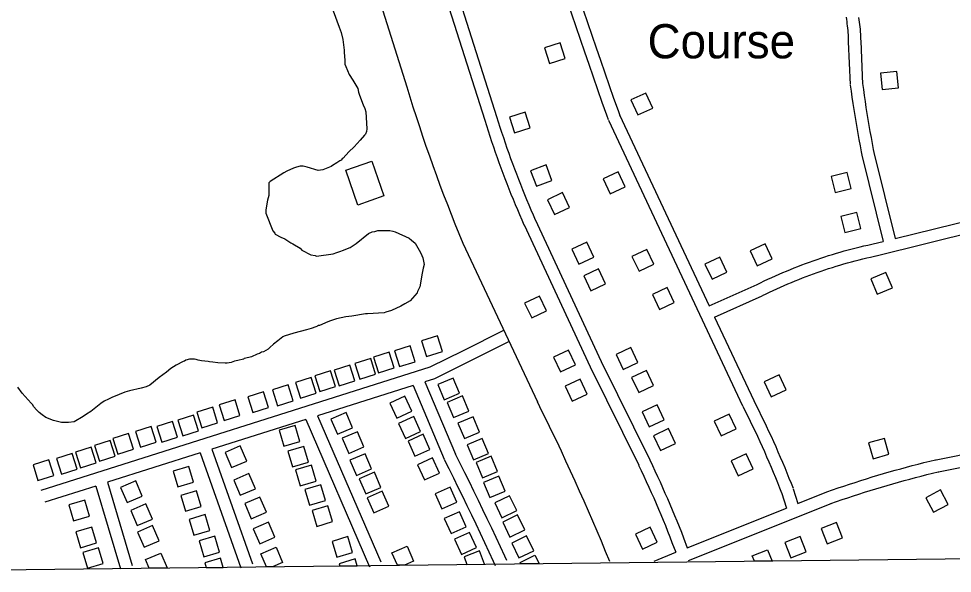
# Model space of a CAD drawing. Extents: x 3683402 to 3721514, y 487807 to 513565.
# Drawn here: x 3688390 to 3690655, y 493222 to 494568 of the extents above; entities that cross this region are included whole.
import ezdxf

# ---------------------------------------------------------------- set-up
doc = ezdxf.new("R2010")
doc.units = 0
for name, color, linetype in [('V-BLDG-IDEN', 7, 'Continuous'), ('V-BLDG-OTLN', 7, 'Continuous'), ('V-GRID-FRAM', 7, 'Continuous'), ('V-ROAD-CNTR', 7, 'Continuous'), ('V-SITE-VEGE', 7, 'Continuous')]:
    doc.layers.add(name, color=color, linetype=linetype)

msp = doc.modelspace()

# ---------------------------------------------------------------- linework, layer by layer
at = {"layer": 'V-BLDG-OTLN'}
for p, q in [((3688977.9, 493269.2), (3689014.6, 493285)), ((3689014.6, 493285), (3689030.5, 493248.3)), ((3689295.7, 493272), (3689332.5, 493287.8)), ((3689332.5, 493287.8), (3689348.3, 493251.1)), ((3689507.8, 493276.1), (3689470.5, 493261.6)), ((3689520.3, 493243.8), (3689507.8, 493276.1)), ((3688697.9, 493255.2), (3688734.7, 493271)), ((3688707, 493234.2), (3688697.9, 493255.2)), ((3688734.7, 493271), (3688750.3, 493234.8)), ((3688879.8, 493259), (3688841.4, 493247.6)), ((3688886.5, 493236.4), (3688879.8, 493259)), ((3688991.5, 493237.6), (3688977.9, 493269.2)), ((3689206, 493256.7), (3689167.6, 493245.3)), ((3689210.9, 493240.2), (3689206, 493256.7)), ((3689309, 493241.3), (3689295.7, 493272)), ((3689470.5, 493261.6), (3689477.6, 493243.3)), ((3689606.6, 493248.1), (3689642.6, 493265.7)), ((3689642.6, 493265.7), (3689652.5, 493245.4)), ((3688750.3, 493234.8), (3688707, 493234.2)), ((3688841.4, 493247.6), (3688844.9, 493235.9)), ((3688844.9, 493235.9), (3688886.5, 493236.4)), ((3689006, 493237.8), (3688991.5, 493237.6)), ((3689030.5, 493248.3), (3689006, 493237.8)), ((3689167.6, 493245.3), (3689169.3, 493239.7)), ((3689169.3, 493239.7), (3689210.9, 493240.2)), ((3689326.1, 493241.5), (3689309, 493241.3)), ((3689348.3, 493251.1), (3689326.1, 493241.5)), ((3689477.6, 493243.3), (3689520.3, 493243.8)), ((3689608.2, 493244.8), (3689606.6, 493248.1)), ((3689652.5, 493245.4), (3689608.2, 493244.8)), ((3690217.9, 493251.7), (3690175.1, 493251.2))]:
    msp.add_line(p, q, dxfattribs=at)
for points in [[(3689715.7, 494471.5), (3689703.7, 494509.7), (3689665.6, 494497.7), (3689677.6, 494459.5)], [(3690480.5, 494435.9), (3690484.6, 494396.1), (3690524.4, 494400.2), (3690520.3, 494440)], [(3689875.5, 494371.1), (3689892.1, 494334.7), (3689928.5, 494351.2), (3689911.9, 494387.7)], [(3689580.8, 494328.9), (3689593, 494290.8), (3689631.1, 494303), (3689618.9, 494341.1)], [(3689276.1, 494137.8), (3689213, 494115.9), (3689183.6, 494200.6), (3689246.7, 494222.5)], [(3689632.1, 494199.1), (3689646, 494161.6), (3689683.5, 494175.5), (3689669.6, 494213)], [(3689861.4, 494160), (3689844.4, 494196.2), (3689808.2, 494179.2), (3689825.2, 494143)], [(3690409.8, 494155.6), (3690400.2, 494194.4), (3690361.4, 494184.8), (3690371, 494146)], [(3689673, 494128.8), (3689690.1, 494092.6), (3689726.3, 494109.7), (3689709.2, 494145.9)], [(3690432.9, 494058.9), (3690423.3, 494097.7), (3690384.4, 494088.2), (3690394, 494049.3)], [(3689732.3, 494008.5), (3689749.4, 493972.3), (3689785.6, 493989.3), (3689768.5, 494025.5)], [(3689931.2, 493971.9), (3689914.2, 494008.1), (3689878, 493991.1), (3689895, 493954.9)], [(3690181.7, 493968.2), (3690218, 493985), (3690201.2, 494021.3), (3690164.9, 494004.6)], [(3690055.1, 493971.9), (3690072.1, 493935.6), (3690108.3, 493952.6), (3690091.3, 493988.9)], [(3689760.8, 493944.1), (3689777.9, 493907.9), (3689814.1, 493924.9), (3689797, 493961.1)], [(3690494.1, 493951.9), (3690457.3, 493936.3), (3690472.9, 493899.5), (3690509.8, 493915.1)], [(3689980.6, 493879.3), (3689963.6, 493915.6), (3689927.4, 493898.6), (3689944.4, 493862.4)], [(3689670.9, 493858.8), (3689653.8, 493895), (3689617.6, 493877.9), (3689634.7, 493841.8)], [(3689379.8, 493748), (3689417.9, 493760), (3689405.8, 493798.2), (3689367.7, 493786.1)], [(3689313.9, 493723.6), (3689352.1, 493735.6), (3689340, 493773.8), (3689301.9, 493761.7)], [(3689263.2, 493708.8), (3689301.3, 493720.9), (3689289.2, 493759), (3689251.1, 493746.9)], [(3689741, 493727.7), (3689724, 493763.9), (3689687.8, 493746.8), (3689704.8, 493710.6)], [(3689839.3, 493752.9), (3689856.3, 493716.7), (3689892.5, 493733.8), (3689875.5, 493770)], [(3689218, 493692.8), (3689256.1, 493704.9), (3689244, 493743), (3689205.9, 493730.9)], [(3689120.7, 493663), (3689158.9, 493675.1), (3689146.8, 493713.3), (3689108.7, 493701.2)], [(3689167.2, 493677), (3689205.3, 493689), (3689193.2, 493727.2), (3689155.1, 493715.1)], [(3689877.2, 493697), (3689894.3, 493660.9), (3689930.5, 493677.9), (3689913.4, 493714.1)], [(3689073.8, 493647.3), (3689112, 493659.4), (3689099.9, 493697.5), (3689061.8, 493685.4)], [(3689407, 493680.2), (3689422.5, 493643.3), (3689459.4, 493658.8), (3689443.9, 493695.7)], [(3689769.4, 493656.6), (3689752.4, 493692.8), (3689716.2, 493675.8), (3689733.2, 493639.6)], [(3690198.5, 493686.6), (3690215.5, 493650.4), (3690251.7, 493667.4), (3690234.7, 493703.6)], [(3688958, 493612.3), (3688996.1, 493624.4), (3688984, 493662.5), (3688945.9, 493650.4)], [(3689017.7, 493628.8), (3689055.9, 493640.9), (3689043.8, 493679), (3689005.6, 493667)], [(3688888.8, 493592.9), (3688926.9, 493604.9), (3688914.9, 493643.1), (3688876.7, 493631)], [(3689343.6, 493615.1), (3689327.2, 493651.6), (3689290.7, 493635.2), (3689307.1, 493598.7)], [(3689429.7, 493636.7), (3689445.2, 493599.9), (3689482.1, 493615.4), (3689466.5, 493652.3)], [(3688834.7, 493574.8), (3688872.8, 493586.8), (3688860.7, 493625), (3688822.6, 493612.9)], [(3689902.6, 493613.6), (3689919.7, 493577.4), (3689955.8, 493594.5), (3689938.8, 493630.6)], [(3688788.4, 493555.8), (3688826.5, 493567.9), (3688814.4, 493606), (3688776.3, 493593.9)], [(3689147.7, 493596.1), (3689163.6, 493559.4), (3689200.3, 493575.3), (3689184.4, 493612)], [(3689364.8, 493565.8), (3689348.4, 493602.3), (3689311.9, 493585.9), (3689328.3, 493549.4)], [(3689455.8, 493586), (3689471.3, 493549.1), (3689508.2, 493564.7), (3689492.6, 493601.5)], [(3690130.9, 493572.2), (3690113.9, 493608.4), (3690077.7, 493591.4), (3690094.7, 493555.2)], [(3688685.8, 493528.1), (3688723.9, 493540.2), (3688711.8, 493578.3), (3688673.7, 493566.2)], [(3688737.2, 493539.9), (3688775.3, 493552), (3688763.2, 493590.1), (3688725.1, 493578)], [(3689071.9, 493542.1), (3689060.5, 493580.4), (3689022.2, 493569.1), (3689033.6, 493530.7)], [(3689930, 493555.9), (3689947.1, 493519.7), (3689983.3, 493536.8), (3689966.2, 493573)], [(3688630.8, 493511), (3688668.9, 493523.1), (3688656.8, 493561.2), (3688618.7, 493549.1)], [(3689175, 493549.9), (3689190.8, 493513.1), (3689227.6, 493529), (3689211.7, 493565.7)], [(3689387.5, 493522.8), (3689371.1, 493559.3), (3689334.6, 493542.9), (3689351, 493506.4)], [(3689477.8, 493533.8), (3689493.3, 493497), (3689530.2, 493512.5), (3689514.6, 493549.3)], [(3690462.8, 493500.1), (3690501.3, 493510.8), (3690490.5, 493549.4), (3690452, 493538.6)], [(3688540.1, 493477.7), (3688578.3, 493489.8), (3688566.2, 493528), (3688528, 493515.9)], [(3688585.8, 493494.1), (3688624, 493506.2), (3688611.9, 493544.3), (3688573.7, 493532.3)], [(3688890.9, 493515.2), (3688906.7, 493478.4), (3688943.5, 493494.3), (3688927.6, 493531)], [(3689093, 493491.4), (3689081.6, 493529.7), (3689043.3, 493518.4), (3689054.7, 493480)], [(3688493.9, 493462.5), (3688532, 493474.6), (3688519.9, 493512.7), (3688481.8, 493500.6)], [(3689193.8, 493496.2), (3689209.7, 493459.4), (3689246.4, 493475.3), (3689230.6, 493512)], [(3689410.6, 493465.3), (3689394.2, 493501.8), (3689357.8, 493485.4), (3689374.2, 493448.9)], [(3689499.8, 493490.7), (3689515.3, 493453.8), (3689552.1, 493469.3), (3689536.6, 493506.2)], [(3690172, 493475.8), (3690155, 493512), (3690118.8, 493495), (3690135.8, 493458.8)], [(3688436.9, 493447), (3688475, 493459.1), (3688462.9, 493497.2), (3688424.8, 493485.1)], [(3688814.4, 493443.1), (3688803, 493481.4), (3688764.7, 493470.1), (3688776, 493431.7)], [(3689111.5, 493445.8), (3689100.1, 493484.2), (3689061.7, 493472.8), (3689073.1, 493434.5)], [(3688911.9, 493448.1), (3688927.7, 493411.3), (3688964.4, 493427.2), (3688948.6, 493463.9)], [(3689216.1, 493451.4), (3689232, 493414.7), (3689268.7, 493430.5), (3689252.9, 493467.3)], [(3689517.9, 493442.5), (3689533.4, 493405.6), (3689570.3, 493421.1), (3689554.8, 493458)], [(3688637.4, 493430.4), (3688653.3, 493393.7), (3688690, 493409.5), (3688674.2, 493446.3)], [(3689134.1, 493398.5), (3689122.7, 493436.8), (3689084.3, 493425.4), (3689095.7, 493387.1)], [(3688832.9, 493384), (3688821.6, 493422.3), (3688783.2, 493410.9), (3688794.6, 493372.6)], [(3689235.5, 493405.4), (3689251.3, 493368.7), (3689288.1, 493384.5), (3689272.2, 493421.2)], [(3689453.1, 493394.5), (3689436.7, 493431), (3689400.2, 493414.6), (3689416.6, 493378.1)], [(3690626.1, 493424.2), (3690590.8, 493405.5), (3690609.5, 493370.2), (3690644.8, 493388.9)], [(3688561.5, 493360.9), (3688550.2, 493399.3), (3688511.8, 493387.9), (3688523.2, 493349.6)], [(3688661.8, 493374.6), (3688677.7, 493337.8), (3688714.4, 493353.7), (3688698.6, 493390.4)], [(3688938.4, 493391.1), (3688954.2, 493354.4), (3688990.9, 493370.2), (3688975.1, 493407)], [(3689545, 493392.6), (3689562.5, 493356.6), (3689598.5, 493374.2), (3689581, 493410.1)], [(3689151.6, 493347.3), (3689140.2, 493385.7), (3689101.9, 493374.3), (3689113.2, 493335.9)], [(3689475.6, 493334.7), (3689459.2, 493371.2), (3689422.7, 493354.8), (3689439.1, 493318.3)], [(3688853.4, 493325.9), (3688842.1, 493364.3), (3688803.7, 493352.9), (3688815.1, 493314.5)], [(3688959.2, 493330.2), (3688975.1, 493293.5), (3689011.8, 493309.3), (3688995.9, 493346.1)], [(3689564.4, 493346), (3689582, 493310), (3689617.9, 493327.6), (3689600.4, 493363.5)], [(3690373.9, 493345.4), (3690336.8, 493330.5), (3690351.7, 493293.4), (3690388.8, 493308.2)], [(3688578.6, 493295.5), (3688567.2, 493333.8), (3688528.9, 493322.5), (3688540.2, 493284.1)], [(3688678.2, 493322), (3688694.1, 493285.3), (3688730.8, 493301.1), (3688715, 493337.8)], [(3689500.5, 493284.3), (3689484.1, 493320.8), (3689447.7, 493304.4), (3689464.1, 493267.9)], [(3689939.4, 493297.6), (3689922.3, 493333.8), (3689886.2, 493316.8), (3689903.2, 493280.6)], [(3688877.3, 493273.4), (3688865.9, 493311.7), (3688827.6, 493300.4), (3688839, 493262)], [(3689200, 493272.6), (3689188.6, 493310.9), (3689150.2, 493299.5), (3689161.6, 493261.2)], [(3689586.3, 493295), (3689603.8, 493259.1), (3689639.7, 493276.6), (3689622.2, 493312.5)], [(3690285.7, 493311.2), (3690248.6, 493296.4), (3690263.5, 493259.2), (3690300.6, 493274.1)], [(3688595.2, 493245.7), (3688583.9, 493284.1), (3688545.5, 493272.7), (3688556.9, 493234.3)]]:
    msp.add_lwpolyline(points, close=True, dxfattribs=at)
for points in [[(3690175.1, 493251.2), (3690169.8, 493264.3), (3690206.9, 493279.2)], [(3690206.9, 493279.2), (3690217.9, 493251.7)]]:
    msp.add_lwpolyline(points, dxfattribs=at)
at = {"layer": 'V-GRID-FRAM'}
msp.add_lwpolyline([(3687448, 511403.5), (3719130.8, 511772.1), (3719350.3, 493590.7), (3687651.7, 493221.8), (3687448, 511403.5)], dxfattribs=at)
at = {"layer": 'V-ROAD-CNTR'}
for points in [[(3689156.9, 494957.3), (3689331.5, 494402.6)], [(3689388.1, 494838.2), (3689549.4, 494330.7)], [(3689359.5, 494829.4), (3689520.8, 494321.6)], [(3689690.6, 494703.3), (3689700.7, 494672.5), (3689710.8, 494641.7), (3689720.9, 494610.9), (3689731.2, 494580.2), (3689741.5, 494549.4), (3689751.9, 494518.7), (3689762.4, 494488), (3689773, 494457.4), (3689783.6, 494426.8), (3689794.4, 494396.2), (3689805.1, 494365.6), (3689816, 494335.1), (3689820.3, 494323.2)], [(3689719.2, 494712.6), (3689729.2, 494681.8), (3689739.3, 494651.1), (3689749.4, 494620.4), (3689759.6, 494589.7), (3689770, 494559), (3689780.3, 494528.4), (3689790.8, 494497.8), (3689801.3, 494467.2), (3689812, 494436.7), (3689822.7, 494406.1), (3689833.4, 494375.6), (3689844.3, 494345.1), (3689848.5, 494333.3)], [(3690397.2, 494571.8), (3690398.1, 494566.5), (3690398.9, 494561.1), (3690399.6, 494555.8), (3690400.3, 494550.5), (3690400.9, 494545.1), (3690401.4, 494539.7), (3690401.8, 494534.4), (3690402.2, 494529), (3690402.5, 494523.6), (3690402.7, 494518.2), (3690402.8, 494512.8), (3690402.8, 494512.5)], [(3690427.7, 494571.2), (3690428.6, 494565.5), (3690429.4, 494559.7), (3690430.1, 494553.9), (3690430.7, 494548.2), (3690431.3, 494542.4), (3690431.8, 494536.6), (3690432.1, 494530.8), (3690432.4, 494525), (3690432.7, 494519.2), (3690432.8, 494513.4), (3690432.8, 494513)], [(3690402.8, 494512.1), (3690407.4, 494408.1)], [(3690432.8, 494513.4), (3690437.4, 494409.4)], [(3690437.3, 494410.7), (3690439.3, 494396.1), (3690441.3, 494381.6), (3690443.5, 494367), (3690445.7, 494352.4), (3690448, 494337.9), (3690450.4, 494323.4), (3690452.8, 494308.9), (3690455.4, 494294.4), (3690458, 494279.9), (3690460.7, 494265.4), (3690463.4, 494251), (3690465, 494243)], [(3690407.5, 494406.7), (3690409.5, 494392), (3690411.6, 494377.3), (3690413.8, 494362.5), (3690416, 494347.8), (3690418.4, 494333.1), (3690420.8, 494318.5), (3690423.2, 494303.8), (3690425.8, 494289.1), (3690428.5, 494274.5), (3690431.2, 494259.9), (3690434, 494245.2), (3690435.5, 494237.2)], [(3689520.8, 494321.7), (3689524.8, 494308.7), (3689528.9, 494295.8), (3689533.1, 494282.9), (3689537.4, 494270), (3689541.8, 494257.1), (3689546.2, 494244.3), (3689550.7, 494231.5), (3689555.3, 494218.7), (3689559.9, 494206), (3689564.7, 494193.2), (3689569.5, 494180.6), (3689574.3, 494167.9), (3689579.3, 494155.2), (3689584.3, 494142.6), (3689589.4, 494130.1), (3689594.6, 494117.5), (3689599.9, 494105), (3689605.2, 494092.5), (3689610.6, 494080.1), (3689615.9, 494068)], [(3689549.4, 494330.6), (3689553.4, 494317.8), (3689557.5, 494305), (3689561.6, 494292.3), (3689565.9, 494279.5), (3689570.1, 494266.8), (3689574.5, 494254.2), (3689579, 494241.5), (3689583.5, 494228.9), (3689588.1, 494216.3), (3689592.7, 494203.8), (3689597.5, 494191.3), (3689602.3, 494178.8), (3689607.2, 494166.3), (3689612.2, 494153.8), (3689617.2, 494141.4), (3689622.3, 494129), (3689627.5, 494116.7), (3689632.8, 494104.4), (3689638.1, 494092.1), (3689643.4, 494080.1)], [(3689820.8, 494321.9), (3690146.3, 493628.3)], [(3689848, 494334.6), (3690065.6, 493870.9)], [(3690435.7, 494236.5), (3690487.3, 494027.6)], [(3690464.8, 494243.7), (3690516.4, 494034.8)], [(3689616, 494067.7), (3689776.2, 493723.3), (3689894.2, 493484.1)], [(3689643.2, 494080.4), (3689803.2, 493736.3), (3689921.1, 493497.4)], [(3690516.4, 494034.8), (3690707.2, 494081.9)], [(3690470.3, 493992.5), (3690714.4, 494052.8)], [(3689467.5, 494023.6), (3689648.6, 493637.8)], [(3690463.1, 494021.6), (3690487.3, 494027.6)], [(3690181.3, 493922.9), (3690190.1, 493927.2), (3690199, 493931.5), (3690207.9, 493935.7), (3690216.9, 493939.8), (3690225.9, 493943.9), (3690234.9, 493947.9), (3690244, 493951.8), (3690253.1, 493955.7), (3690262.2, 493959.4), (3690271.4, 493963.1), (3690280.6, 493966.8), (3690289.8, 493970.3), (3690299, 493973.8), (3690308.3, 493977.2), (3690317.6, 493980.5), (3690326.9, 493983.7), (3690336.3, 493986.9), (3690345.7, 493990), (3690355.1, 493993), (3690364.5, 493995.9), (3690374, 493998.8), (3690383.4, 494001.5), (3690392.9, 494004.3), (3690402.5, 494006.9), (3690412, 494009.4), (3690421.6, 494011.9), (3690431.2, 494014.3), (3690440.8, 494016.6), (3690450.4, 494018.8), (3690460, 494021), (3690463.5, 494021.7)], [(3690194.5, 493895.9), (3690203.2, 493900.2), (3690211.9, 493904.4), (3690220.6, 493908.5), (3690229.3, 493912.5), (3690238.1, 493916.5), (3690246.9, 493920.4), (3690255.8, 493924.2), (3690264.6, 493928), (3690273.5, 493931.7), (3690282.5, 493935.3), (3690291.4, 493938.8), (3690300.4, 493942.3), (3690309.4, 493945.6), (3690318.5, 493948.9), (3690327.6, 493952.2), (3690336.7, 493955.3), (3690345.8, 493958.4), (3690354.9, 493961.4), (3690364.1, 493964.4), (3690373.3, 493967.2), (3690382.5, 493970), (3690391.8, 493972.7), (3690401, 493975.4), (3690410.3, 493977.9), (3690419.6, 493980.4), (3690428.9, 493982.8), (3690438.3, 493985.1), (3690447.7, 493987.4), (3690457, 493989.6), (3690466.5, 493991.7), (3690469.9, 493992.4)], [(3690065.6, 493870.9), (3690181.7, 493923.1)], [(3690078.4, 493843.7), (3690194, 493895.7)], [(3690078.4, 493843.7), (3690173.5, 493641.1)], [(3689566.6, 493811.4), (3689468.2, 493761.9), (3689387.6, 493722.2), (3688444.1, 493423.1)], [(3689580.1, 493784.6), (3689481.5, 493735), (3689398.8, 493694.3), (3689375.6, 493686.9)], [(3689375.6, 493686.9), (3689449.7, 493510.8)], [(3689346.9, 493677.8), (3689115.3, 493604.4)], [(3689346.9, 493677.8), (3689422.1, 493499.1)], [(3690173.3, 493641.5), (3690179.5, 493629.2), (3690185.7, 493616.8), (3690191.7, 493604.5), (3690197.7, 493592), (3690203.7, 493579.6), (3690209.5, 493567.1), (3690215.3, 493554.6), (3690221, 493542), (3690226.7, 493529.4), (3690232.2, 493516.8), (3690237.7, 493504.1), (3690243.1, 493491.5), (3690248.5, 493478.7), (3690253.7, 493466), (3690258.9, 493453.2), (3690264, 493440.4), (3690268.8, 493428.2)], [(3690146.5, 493627.9), (3690152.7, 493615.7), (3690158.8, 493603.5), (3690164.8, 493591.3), (3690170.7, 493579.1), (3690176.5, 493566.8), (3690182.3, 493554.4), (3690188, 493542.1), (3690193.7, 493529.7), (3690199.2, 493517.2), (3690204.7, 493504.8), (3690210.2, 493492.3), (3690215.5, 493479.8), (3690220.8, 493467.2), (3690226, 493454.6), (3690231.1, 493442), (3690236.2, 493429.4), (3690240.9, 493417.3)], [(3689086.6, 493595.3), (3688858.7, 493523)], [(3689086.6, 493595.3), (3689240.8, 493237.9)], [(3689115.3, 493604.4), (3689268.3, 493249.8)], [(3688830.1, 493514), (3688605.8, 493442.9)], [(3688830.1, 493514), (3688928.7, 493235.2)], [(3688858.7, 493523), (3688957, 493245.2)], [(3689449.3, 493511.7), (3689460.5, 493489.3), (3689471.6, 493467), (3689482.7, 493444.6), (3689493.6, 493422.1), (3689504.5, 493399.6), (3689515.4, 493377.1), (3689526.1, 493354.6), (3689536.8, 493332), (3689547.4, 493309.3), (3689557.9, 493286.7), (3689568.4, 493264), (3689573.2, 493253.6)], [(3690615.8, 493497.7), (3690724.7, 493519.2)], [(3689422.5, 493498.2), (3689433.7, 493476), (3689444.7, 493453.7), (3689455.7, 493431.3), (3689466.7, 493409), (3689477.5, 493386.6), (3689488.3, 493364.2), (3689499, 493341.7), (3689509.7, 493319.2), (3689520.2, 493296.7), (3689530.7, 493274.1), (3689541.2, 493251.5), (3689545.9, 493241.1)], [(3689894.1, 493484.4), (3689900.4, 493471.1), (3689906.6, 493457.9), (3689912.7, 493444.7), (3689918.7, 493431.4), (3689924.7, 493418.1), (3689930.6, 493404.8), (3689936.4, 493391.4), (3689942.1, 493378), (3689947.8, 493364.6), (3689953.4, 493351.2), (3689958.9, 493337.7), (3689964.4, 493324.1), (3689969.7, 493310.6), (3689975, 493297), (3689984.3, 493272.9)], [(3689921.2, 493497.2), (3689927.5, 493483.9), (3689933.8, 493470.6), (3689940, 493457.2), (3689946.1, 493443.8), (3689952.1, 493430.3), (3689958, 493416.8), (3689963.9, 493403.3), (3689969.7, 493389.8), (3689975.5, 493376.2), (3689981.1, 493362.6), (3689986.7, 493349), (3689992.2, 493335.3), (3689997.7, 493321.6), (3690003, 493307.8), (3690012.2, 493284)], [(3690350.9, 493419.6), (3690364.5, 493424.3), (3690378.2, 493429.1), (3690391.9, 493433.7), (3690405.6, 493438.2), (3690419.3, 493442.7), (3690433.1, 493447.1), (3690446.9, 493451.5), (3690460.7, 493455.7), (3690474.6, 493459.9), (3690488.4, 493464), (3690502.3, 493468), (3690516.3, 493472), (3690530.2, 493475.8), (3690544.2, 493479.6), (3690558.1, 493483.3), (3690572.1, 493487), (3690586.1, 493490.5), (3690600.2, 493494), (3690614.2, 493497.4), (3690615.2, 493497.6)], [(3690621.6, 493468.3), (3690730.5, 493489.7)], [(3690360.8, 493391.3), (3690374.3, 493396), (3690387.9, 493400.7), (3690401.4, 493405.2), (3690415, 493409.8), (3690428.6, 493414.2), (3690442.2, 493418.5), (3690455.8, 493422.8), (3690469.5, 493427), (3690483.2, 493431.1), (3690496.9, 493435.2), (3690510.6, 493439.2), (3690524.4, 493443.1), (3690538.1, 493446.9), (3690551.9, 493450.6), (3690565.7, 493454.3), (3690579.6, 493457.9), (3690593.4, 493461.4), (3690607.3, 493464.8), (3690621.2, 493468.2), (3690622.1, 493468.4)], [(3688577.2, 493433.8), (3688453.2, 493394.5)], [(3688577.2, 493433.8), (3688637, 493232.6)], [(3688605.8, 493442.9), (3688665.7, 493241.1)], [(3690240.6, 493418.2), (3690252.7, 493380.3)], [(3690269.2, 493427.3), (3690280.6, 493391.4)], [(3690280.6, 493391.4), (3690350.3, 493419.3)], [(3690014.7, 493252.7), (3690361.4, 493391.5)], [(3690012.2, 493284), (3690252.7, 493380.3)], [(3689931.5, 493251.7), (3689984.3, 493272.9)]]:
    msp.add_lwpolyline(points, dxfattribs=at)
for centre, radius, start, end in [((3693231.5, 495587.1), 4075.8, 196.8948, 202.5584), ((3684737.9, 491181.9), 5490.6, 22.1319, 26.5702)]:
    msp.add_arc(centre, radius, start, end, dxfattribs=at)
at = {"layer": 'V-SITE-VEGE'}
for points in [[(3689152.7, 494587.3), (3689167.9, 494547.6), (3689172.3, 494534.7), (3689176.6, 494517.6), (3689180, 494491.8)], [(3689180, 494491.8), (3689180, 494486.4), (3689181.2, 494467.1), (3689181.2, 494457.4), (3689183.4, 494452.1), (3689192.1, 494432.8), (3689200.7, 494418.9), (3689212.6, 494398.5), (3689214.8, 494389.9), (3689217, 494382.4), (3689225.7, 494358.8), (3689230, 494350.3), (3689232.2, 494341.7), (3689234.6, 494300.9), (3689233.5, 494294.4), (3689231.4, 494288), (3689229.3, 494285.8), (3689218.6, 494272.9), (3689203.6, 494256.7), (3689190.8, 494244.8), (3689176.9, 494229.7), (3689174.8, 494227.6), (3689172.6, 494224.4), (3689169.4, 494223.3), (3689161.9, 494217.9), (3689151.2, 494211.4), (3689148, 494209.2), (3689127.6, 494201.6), (3689116.9, 494199.4), (3689090, 494207.9), (3689080.3, 494210), (3689072.8, 494209.9), (3689064.2, 494207.7), (3689056.7, 494205.6), (3689040.7, 494198), (3689033.2, 494193.6), (3689000, 494173.1), (3688996.8, 494169.8), (3688996.8, 494151.6), (3688996.9, 494138.7), (3688993.7, 494127.9), (3688989.6, 494104.3), (3688989.6, 494095.7), (3689007, 494052.8), (3689011.3, 494047.5), (3689012.4, 494045.3), (3689026.4, 494037.9), (3689036.1, 494033.6), (3689050.1, 494024), (3689055.4, 494021.9), (3689072.7, 494011.2), (3689077, 494005.9), (3689098.5, 493995.3), (3689109.3, 493993.2), (3689112.5, 493992.1), (3689153.3, 493997.7), (3689161.9, 494000.9), (3689171.5, 494004.2), (3689175.8, 494005.3), (3689194, 494012.9), (3689209, 494022.6), (3689239, 494046.4), (3689247.5, 494050.7), (3689254, 494051.8), (3689261.5, 494054), (3689290.5, 494054.1), (3689298, 494052), (3689303.4, 494051), (3689337.8, 494035), (3689343.2, 494030.8), (3689351.8, 494023.3), (3689355.1, 494017.9), (3689364.8, 494000.8), (3689368.1, 493993.3), (3689370.3, 493987.9), (3689373.6, 493971.8), (3689371.5, 493962.2), (3689368.3, 493946), (3689367.3, 493940.7), (3689363.1, 493917), (3689357.8, 493906.2), (3689356.7, 493903), (3689339.6, 493883.6), (3689326.8, 493876), (3689317.1, 493870.6), (3689294.6, 493859.8), (3689280.7, 493855.4), (3689276.4, 493854.3), (3689236.7, 493852), (3689231.3, 493852), (3689198, 493846.4), (3689184.1, 493844.2), (3689161.5, 493839.8), (3689146.5, 493834.4), (3689140.1, 493832.2), (3689119.7, 493823.5), (3689117.6, 493823.5), (3689115.4, 493821.4), (3689111.1, 493820.3), (3689099.4, 493815.9), (3689088.6, 493812.6)], [(3689088.6, 493812.6), (3689057.5, 493805), (3689033.9, 493797.3), (3689030.7, 493796.3), (3689018.9, 493786.5), (3689008.2, 493777.9), (3688999.7, 493770.3), (3688995.4, 493766), (3688983.6, 493759.5), (3688979.3, 493758.4), (3688974, 493755.2), (3688968.6, 493754.1), (3688954.7, 493747.6), (3688948.3, 493745.4), (3688937.5, 493743.2), (3688935.4, 493742.1), (3688921.4, 493738.8), (3688913.9, 493736.7), (3688905.4, 493733.4), (3688895.7, 493732.3), (3688891.4, 493732.2), (3688873.1, 493733.2), (3688861.3, 493734.3), (3688852.7, 493735.3), (3688849.5, 493736.4), (3688833.4, 493737.3), (3688825.9, 493739.5), (3688820.5, 493740.5), (3688816.2, 493741.6), (3688804.4, 493741.5), (3688795.8, 493739.3), (3688792.6, 493737.2), (3688789.4, 493736.1), (3688772.2, 493727.4), (3688759.4, 493718.7), (3688748.7, 493710.1), (3688730.5, 493697.1), (3688708, 493678.8), (3688699.4, 493674.4), (3688687.6, 493671.2), (3688658.7, 493664.6), (3688647.9, 493661.3), (3688634, 493655.9), (3688615.8, 493648.3), (3688608.3, 493645), (3688597.6, 493639.6), (3688589, 493634.2), (3688565.5, 493614.7), (3688554.8, 493608.3), (3688546.2, 493602.8), (3688524.8, 493589.9), (3688510.8, 493587.6), (3688493.6, 493587.6), (3688474.3, 493592.8), (3688456, 493600.3), (3688447.4, 493606.7), (3688439.8, 493612), (3688433.3, 493618.4), (3688426.9, 493625.9), (3688423.6, 493631.3), (3688420.4, 493634.5), (3688398.8, 493659.1), (3688388, 493674.1)]]:
    msp.add_lwpolyline(points, dxfattribs=at)

# ---------------------------------------------------------------- texts
at = {"layer": 'V-BLDG-IDEN'}
msp.add_text('Course', height=83, dxfattribs=at).set_placement((3689915.8, 494471.9))

doc.saveas('drawing.dxf')
